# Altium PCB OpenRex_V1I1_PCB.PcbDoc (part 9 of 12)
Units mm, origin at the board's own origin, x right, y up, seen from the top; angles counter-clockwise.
Board outline 70 x 95 mm, 10 copper layers (L1, L2, L3, L4 (PWR), L5 (PWR), L6 (PWR), L7 (PWR), L8, L9, L10), stack 1.632 mm thick; 1080 components, 708 nets, 3831 pads, 2373 vias.
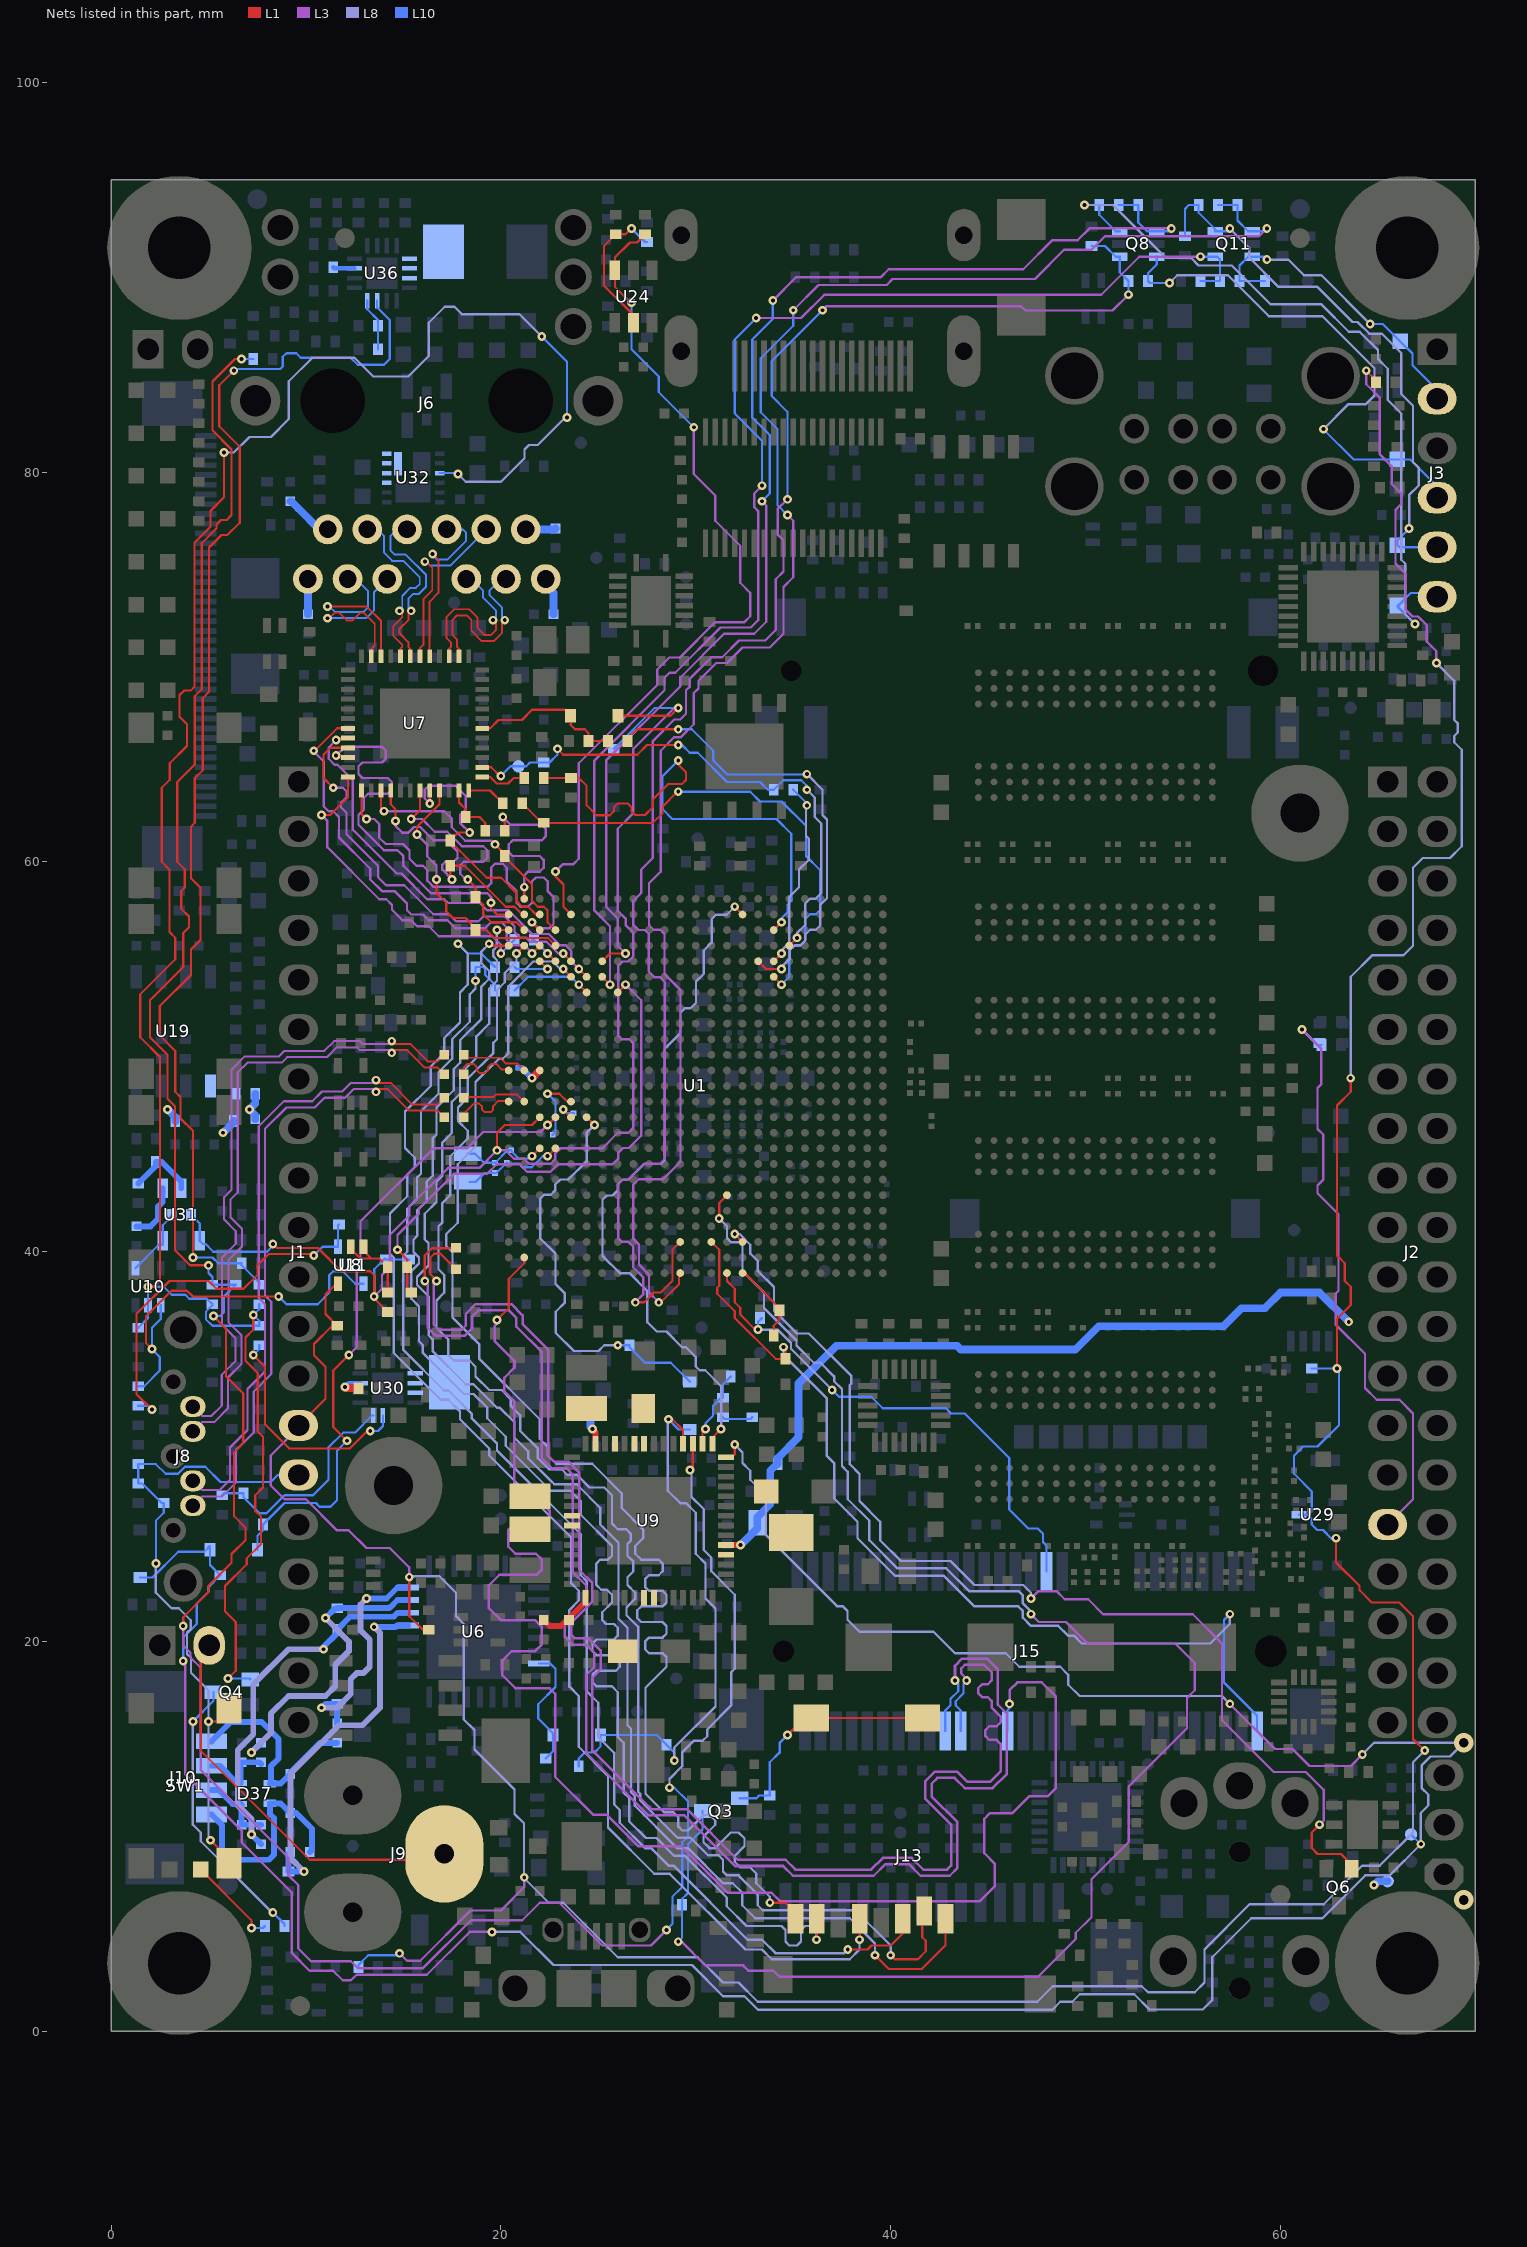
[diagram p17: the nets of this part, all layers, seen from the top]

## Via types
v1: diameter 0.45, hole 0.2, L1 to L10, tented both sides, 2369 vias
v2: diameter 1, hole 0.5, L1 to L10, tented top, 4 vias

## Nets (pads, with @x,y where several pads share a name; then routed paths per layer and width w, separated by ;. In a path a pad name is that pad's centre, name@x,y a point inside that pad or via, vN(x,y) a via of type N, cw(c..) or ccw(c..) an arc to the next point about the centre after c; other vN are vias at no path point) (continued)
PCIE_RX_P: J15.25 U1.B2 | length 83.6
  L1 w0.114: v1(19.8,36.5) 20.4,37.1 20.4,38.605 21.2,39.405 U1.B2@21.2,39.7
  L3 w0.13: v1(19.8,36.5) 19.8,36.3 19.679,36.179 19.679,35.421 20.7,34.4 20.7,34.053 20.18,33.533 20.18,32.82 20.69,32.31 20.69,27.802 21.192,27.3 21.9,27.3 22.5,26.7 22.5,26.4 22.32,26.22 20.867,26.22 20.38,25.733 20.38,24.867 20.747,24.5 21.8,24.5 22.1,24.2 22.1,23.7 21.82,23.42 19.917,23.42 19.38,22.883 19.38,21.717 19.997,21.1 21.747,21.1 22.1,20.747 22.1,19.853 21.757,19.51 20.557,19.51 20.08,19.033 20.08,18.267 20.747,17.6 22.5,17.6 22.79,17.31 22.79,13.057 24.747,11.1 25.447,11.1 27.047,9.5 29.247,9.5 31.647,7.1 33.9,7.1 34.32,6.68 44.58,6.68 45.35,7.45 45.35,8.59 44.8,9.14 44.8,10.9 45.08,11.18 46.233,11.18 47.1,12.047 48.047,12.047 48.476,12.476 48.476,17.177 47.753,17.9 46.5,17.9 46.1,17.5 v1(46.1,16.8)
  L10 w0.114: J15.25@46,15.4 46,16.49 46.1,16.59 v1(46.1,16.8)
PCIE_TX_N: C63.2 J15.31 | length 80.7
  L1 w0.114: v1(16.7,38.5) 16.7,38.525 16.374,38.851 16.374,39.687 16.583,39.896 16.904,39.896 C63.2@17.7,39.1
  L3 w0.13: v1(16.7,38.5) 16.56,38.36 16.56,36.24 16.8,36 18,36 18.2,36.2 18.2,36.8 18.71,37.31 20.543,37.31 21.12,36.733 21.12,36.28 22.42,34.98 22.42,29.528 22.738,29.21 23.49,29.21 24.02,28.68 24.02,23.68 24.7,23 24.7,22.047 23.6,20.947 23.6,20.36 23.8,20.16 24.503,20.16 25.12,19.543 25.12,18.567 24.7,18.147 24.7,14.4 27.7,11.4 29.553,11.4 32.153,8.8 34.613,8.8 35.113,8.3 39,8.3 39.6,8.9 41.072,8.9 41.672,8.3 42.9,8.3 43.1,8.5 43.1,10.6 41.78,11.92 41.78,12.833 42.267,13.32 43.413,13.32 43.933,12.8 45.1,12.8 45.64,13.34 45.64,14.75 45.44,14.95 45.057,14.95 44.857,15.15 44.857,15.45 45.057,15.65 45.44,15.65 45.64,15.85 45.64,16.16 45.18,16.62 45.18,16.95 44.98,17.15 44.69,17.15 44.49,17.35 44.49,17.6 44.69,17.8 44.98,17.8 45.18,18 45.18,18.42 44.8,18.8 43.8,18.8 43.62,18.62 43.62,18.359 43.9,18.079 v1(43.9,18)
  L10 w0.114: J15.31@43.6,15.4 43.6,16.457 43.337,16.72 43.337,16.937 43.737,17.337 43.737,17.837 v1(43.9,18)
PCIE_TX_P: C65.2 J15.33 | length 80.7
  L1 w0.114: v1(16.1,38.5) 16.1,39.8 16.47,40.17 17.67,40.17 C65.2@17.7,40.2
  L3 w0.13: v1(16.1,38.5) 16.24,38.36 16.24,36.107 16.667,35.68 18.133,35.68 18.52,36.067 18.52,36.667 18.843,36.99 20.41,36.99 20.8,36.6 20.8,36.147 22.1,34.847 22.1,29.396 22.606,28.89 23.357,28.89 23.7,28.547 23.7,23.547 24.38,22.867 24.38,22.18 23.28,21.08 23.28,20.227 23.667,19.84 24.37,19.84 24.8,19.41 24.8,18.7 24.38,18.28 24.38,14.267 27.567,11.08 29.42,11.08 32.02,8.48 34.48,8.48 34.98,7.98 39.133,7.98 39.733,8.58 40.939,8.58 41.539,7.98 43.033,7.98 43.42,8.367 43.42,10.733 42.1,12.053 42.1,12.7 42.4,13 43.281,13 43.801,12.48 45.233,12.48 45.96,13.207 45.96,16.293 45.5,16.753 45.5,18.553 44.933,19.12 43.667,19.12 43.3,18.753 v1(43.3,18)
  L10 w0.114: J15.33@42.8,15.4 42.8,16.457 43.063,16.72 43.063,17.05 43.463,17.45 43.463,17.837 v1(43.3,18)
PCIE_WAKE: J15.1 R197.1 U1.P3 | length 49.2
  L1 w0.114: U1.P3@30.8,40.5 31.2,40.1 31.2,38.244 31.1,38.144 31.1,37.844 32,36.944 32,36.6 34.1,34.5 R197.1@34.6,34.5 34.6,35 v1(34.5,35.1)
  L8 w0.12: v1(34.5,35.1) 34.5,34.7 36.715,32.485 36.715,29.541 37.1,29.156 37.1,27.344 38.3,26.144 38.3,25.3 40.234,23.366 42.734,23.366 44.3,21.8 46.544,21.8 46.785,21.559 46.785,21.215 47.2,20.8 48.6,20.8 49.1,20.3 49.4,20.3 49.8,19.9 56.4,19.9 57.4,20.9 v1(57.4,21.4)
  L10 w0.114: v1(57.4,21.4) 57.1,21.1 57.1,17.9 58.8,16.2 J15.1@58.8,15.4
PCIE_WDISN: J15.20 R116.1 U1.R1 | length 27
  L1 w0.114: U1.R1@31.6,38.9 31.6,38.5 32,38.1 32,37.4 32.28,37.12 32.28,36.776 33.056,36 v1(33.2,36)
  L8 w0.12: v1(33.2,36) 34.2,36 34.885,35.315 34.885,35.015 v1(37,32.9)
  L10 w0.114: v1(33.2,36) 33.2,36.4 R116.1@33.4,36.6 ; v1(37,32.9) 37.344,32.556 39,32.556 39.591,31.965 42.835,31.965 43.1,31.7 43.8,31.7 46.085,29.415 46.085,26.77 47.056,25.8 47.544,25.8 47.815,25.529 47.815,25.1 48,24.915 J15.20@48,23.6
PHASE_1V375: L12.1 U30.13 U30.14 U30.15
PHASE_3V3_HDR: L13.1 U36.13 U36.14 U36.15
PMIC_INT: R236.2 R263.1 U1.T24 U9.1 | length 37.8
  L1 w0.114: U9.1@30.85,30.15 30.85,30.45 v1(31.3,30.9) ; v1(32,57.7) U1.T24@32.4,57.3
  L8 w0.12: v1@31.3,31.1 31.3,33.1 30.485,33.915 30.2,33.915 30,34.115 30,34.6 29.5,35.1 29.3,35.1 28.5,35.9 28,35.9 27.515,36.385 27.515,37.985 26.6,38.9 26.1,38.9 25.215,39.785 25.215,42.659 25.441,42.885 25.729,42.885 25.985,43.141 25.985,43.429 26.241,43.685 26.529,43.685 27.344,44.5 28.2,44.5 28.4,44.7 28.4,50.4 29.215,51.215 29.215,52.259 29.441,52.485 29.729,52.485 30.015,52.771 30.015,53.859 30.408,54.252 30.408,55.448 30.815,55.855 30.815,56.7 30.815,57.059 31.041,57.285 31.585,57.285 v1(32,57.7)
  L10 w0.114: v1(31.3,30.9) 31.3,31.4 R236.2@31.4,31.5 31.485,31.415 32.815,31.415 R263.1@32.9,31.5
PMIC_ON_REQ: D29.1 R73.1 U1.D11 | length 33.5
  L1 w0.114: v1(12.1,30.3) 11.4,31 11.4,33.9 v1(12.2,34.7) ; v1(22.4,46.5) U1.D11@22.8,46.9
  L3 w0.12: v1(12.2,34.7) 12.6,35.1 12.6,39 12.8,39.2 12.8,41.556 16.544,45.3 18.256,45.3 19.096,46.14 22.04,46.14 v1(22.4,46.5)
  L10 w0.114: D29.1@7.519,24.7 7.519,25.419 7.8,25.7 R73.1@7.8,26 8.9,27.1 10.515,27.1 10.7,26.915 11.259,26.915 11.6,27.256 11.6,29.8 v1(12.1,30.3)
PMIC_SDWNB: R236.1 R264.1 U9.2 | length 4.1
  L1 w0.114: U9.2@30.35,30.15 30.35,30.75 v1(30.5,30.9)
  L10 w0.114: v1(30.5,30.9) 30.5,31.2 30.885,31.585 30.885,32.085 31.3,32.5 R236.1@31.4,32.5 31.4,33.2 R264.1@31.8,33.6
PMIC_STBY_REQ: D28.2 D36.2 R237.2 R385.1 U9.4 | length 29.5
  L1 w0.114: v1(28.6,31.4) 28.8,31.4 29.35,30.85 U9.4@29.35,30.15
  L8 w0.12: v1(28.6,31.4) 28.565,31.365 28.565,27.735 29.2,27.1 29.5,27.1 30,26.6 30,24.5 30.5,24 30.5,22.2 31.015,21.685 31.015,16.671 28.9,14.556 v1(28.9,13.9)
  L10 w0.114: R237.2@24,13.6 24,14 24.3,14.3 24.8,14.3 25.119,14.619 D36.2@25.119,15.2 28,15.2 R385.1@28.5,14.7 28.9,14.3 v1(28.9,13.9) ; v1(28.6,31.4) 29.119,30.881 D28.2@29.7,30.881
PMIC_STBY_REQ_CPU: D28.1 R266.1 U1.F11 | length 21.8
  L1 w0.114: U1.F11@24.4,46.9 v1(24.8,46.5)
  L8 w0.12: v1(24.8,46.5) 24.415,46.115 24.415,44.655 23.46,43.7 23.056,43.7 22.785,43.429 22.785,43.141 22.559,42.915 22.211,42.915 22.015,42.719 22.015,40.685 22.8,39.9 22.8,38.344 23.285,37.859 23.285,37.385 22.815,36.915 22.815,35.83 23.745,34.9 25.004,34.9 25.304,35.2 v1(26,35.2)
  L10 w0.114: v1(26,35.2) R266.1@26.6,35.2 26.6,35.1 27.4,34.3 28.719,34.3 D28.1@29.7,33.319
PMIC_VDDOTP: C376.1 R261.1 R265.2 TP17.1 U9.47 | length 42.1
  L1 w0.3: U9.47@31.55,24.95 v1(32.3,24.95)
  L1 w0.4: v2@69.35,6.75 v2@69.4,6.7
  L10 w0.4: v1(32.3,24.95) 33.15,25.8 33.15,26.366 33.82,27.036 33.82,28.76 R265.2@34.2,29.14 ; R265.2@34.2,29.1 R265.2@34.2,29.14 ; v1(63.5,36.4) 62,37.9 60,37.9 59.2,37.1 58,37.1 57.075,36.175 50.675,36.175 49.475,34.975 43.6,34.975 43.4,35.175 37.217,35.175 35.275,33.233 35.275,30.475 34.2,29.4 R265.2@34.2,29.14 ; v1(64.8,7.5) 65,7.7 TP17.1@65.5,7.7
  other v2: 69.4,6.74
PMIC_VHALF: C340.2 C342.1 U9.29 | length 3
  L1 w0.3: C342.1@22.2,21.1 22.5,20.8 23.1,20.8 24.35,22.05 U9.29@24.35,22.25
POK_1V375_OPT: R351.1 U30.3 | length 12
  L1 w0.114: v1(7.3,34.7) 7.9,34.1 7.9,31.144 9.144,29.9 12.244,29.9 13.144,30.8 v1(13.3,30.8)
  L10 w0.114: v1(7.3,34.7) 7.6,35 R351.1@7.6,35.2 ; v1(13.3,30.8) 13.7,30.8 13.95,31.05 U30.3@13.95,31.59
POK_3V3_OPT: R333.1 R405.1 U36.3 | length 65.6
  L1 w0.114: v1(4.2,39.7) 4.2,46.2 3.565,46.835 3.565,47.935 3.3,48.2 3.3,50.3 2.5,51.1 2.5,52.6 4.1,54.2 4.1,55.5 4.585,55.985 4.585,58.675 4.1,59.16 4.1,61.8 4.3,62 4.3,64.3 4.7,64.7 4.7,68.396 5.028,68.724 5.028,76.13 5.663,76.765 5.965,76.765 6.6,77.4 6.6,81.3 5.55,82.35 5.55,84.45 v1(6.3,85.2)
  L10 w0.114: v1(4.2,39.7) 5.2,39.7 5.5,39.4 R405.1@6.7,39.4 6.7,39.3 7.6,38.4 R333.1@7.6,38.3 ; v1(6.3,85.2) 6.385,85.285 8.685,85.285 8.815,85.415 8.815,85.915 9,86.1 9.5,86.1 9.733,85.867 12.289,85.867 12.656,85.5 14,85.5 14.3,85.8 14.3,87.8 13.65,88.45 U36.3@13.65,88.8
POK_PMIC: R177.1 R229.1 R404.2 U9.3 | length 145.1
  L1 w0.114: v1(3.7,20.8) 3.7,21.244 5,22.544 5,22.856 6.185,24.041 6.185,24.485 6.9,25.2 6.9,25.84 6.315,26.425 6.315,29.715 6.785,30.185 6.785,32.719 5.9,33.604 5.9,36.05 v1(5.25,36.7) ; v1(5,39.3) 4.056,39.3 3.285,40.071 3.285,47.459 2.9,47.844 2.9,50.1 2,51 2,52.9 3.7,54.6 3.7,56.344 4,56.644 4,57.2 3.6,57.6 3.6,58.494 3.785,58.679 3.785,59.615 3.4,60 3.4,64.1 4.3,65 4.3,68.5 4.657,68.857 4.657,76.351 5.415,77.109 5.415,77.309 5.641,77.535 5.929,77.535 6.185,77.791 6.185,81.159 5.2,82.144 5.2,84.644 6.356,85.8 v1(6.7,85.8) ; v1(29.7,28.8) 29.85,28.95 U9.3@29.85,30.15
  L3 w0.12: v1(3.7,20.8) 3.7,19.8 4.08,19.42 4.08,19.169 4.6,18.649 4.6,13.4 9.1,8.9 9.1,8 9.6,7.5 9.6,4.256 10.262,3.594 12.3,3.594 12.654,3.24 16.008,3.24 18.468,5.7 21.1,5.7 22,6.6 23,6.6 25.2,4.4 27.7,4.4 v1(28.5,5.2)
  L8 w0.12: v1(28.65,12.5) 28.65,12.95 29.3,13.6 29.3,14.3 29.915,14.915 30.359,14.915 30.585,15.141 30.585,15.485 31.815,16.715 31.815,18.415 32,18.6 32,22.4 30.8,23.6 30.8,24.3 30.406,24.694 30.406,26.794 29.785,27.415 29.785,28.715 v1(29.7,28.8)
  L10 w0.114: v1(5,39.3) 5,38.9 5.2,38.7 R177.1@5.2,38.3 R229.1@6.4,38.3 5.8,37.7 5.8,36.9 5.6,36.7 v1(5.25,36.7) ; v1(6.7,85.8) R404.2@7.3,85.8 ; v1(28.5,5.2) 28.8,5.5 28.8,6.9 29.304,7.404 29.304,9.7 29.6,9.996 29.6,11.8 28.9,12.5 v1(28.65,12.5)
POK_SYS: Q4.1 R177.2 R272.1 R333.2 R351.2 U10.2 U32.9 | length 115.5
  L1 w0.114: v1(1.9,38.2) 2.2,38.2 2.51,38.51 2.51,49.99 1.5,51 1.5,53.2 3.3,55 3.3,56.1 3,56.4 3,59.6 2.6,60 2.6,63.8 3.015,64.215 3.015,65.059 3.9,65.944 3.9,67.056 3.515,67.441 3.515,68.559 3.741,68.785 4.085,68.785 4.285,68.985 4.285,76.375 5.1,77.19 5.1,78 5.8,78.7 v1(5.8,81) ; v1(6,18.1) 6.4,18.5 6.4,21 5.85,21.55 5.85,22.85 6.96,23.96 6.96,24.264 7.7,25.004 7.7,26.4 7.4,26.7 7.4,27.5 7.8,27.9 7.8,30.5 7.528,30.772 7.528,33.772 6.9,34.4 6.9,35.6 7.3,36 v1(7.3,36.75)
  L8 w0.12: v1(5.8,81) 6.3,81 7.1,81.8 8.2,81.8 9.122,82.722 9.122,84.657 10.332,85.867 12.489,85.867 13.456,84.9 15.244,84.9 16.3,85.956 16.3,87.66 17.125,88.485 17.615,88.485 18,88.1 20.95,88.1 v1(22.1,86.95) ; v1(17.8,79.9) 18.2,79.5 20.008,79.5 21.215,80.707 21.215,81.159 21.441,81.385 21.893,81.385 23.308,82.8 v1(23.4,82.8)
  L10 w0.114: R272.1@1.4,36.1 1.9,36.6 U10.2@1.9,37.25 v1(1.9,38.2) 2.7,38.2 3.115,37.785 3.815,37.785 4.015,37.585 4.915,37.585 R177.2@5.2,37.3 5.2,37.256 4.865,36.921 4.865,36.535 5.2,36.2 R351.2@7.6,36.2 7.6,36.45 v1(7.3,36.75) 7.6,37.05 R333.2@7.6,37.3 ; v1(6,18.1) 7.1,18.1 Q4.1@7.15,18.05 ; U32.9@16.86,79.95 17.75,79.95 v1(17.8,79.9) ; v1(22.1,86.95) 23.4,85.65 v1(23.4,82.8)
POR_BN: D10.1 R70.1 R158.1 R178.2 R225.1 R350.1 U1.C11 U31.1 | length 71.7
  L1 w0.114: v1(8.3,40.4) 8.515,40.185 10.615,40.185 11.8,39 13.3,39 13.5,38.8 v1(13.5,37.7) 13.5,37.6 R70.1@14.2,36.9 ; v1(19.8,45.2) 19.8,46.1 20.2,46.5 21.6,46.5 U1.C11@22,46.9 ; D10.1@25.919,67.5 D10.1@25.969,67.55 ; D10.1@26.019,67.5 28.7,67.5 v1(29.1,67.9)
  L3 w0.12: v1(13.5,37.7) 13.9,38.1 13.9,38.8 14.3,39.2 14.3,40.856 15.3,41.856 15.3,42.3 17.3,44.3 18.9,44.3 v1(19.8,45.2) 20.244,45.2 20.679,44.765 21.191,44.765 21.441,44.515 22.559,44.515 22.785,44.741 22.785,45.029 23.056,45.3 25.2,45.3 26,46.1 26.544,46.1 26.785,46.341 26.785,50.7 26.585,50.9 26.2,50.9 26.015,51.085 26.015,54.659 26.241,54.885 26.529,54.885 26.8,55.156 26.8,56.36 26.4,56.76 26.4,57.096 26,57.496 26,61.7 26.8,62.5 26.8,65.8 28.9,67.9 v1(29.1,67.9)
  L10 w0.114: R350.1@4.1,41.9 4.55,41.45 U31.1@4.55,40.55 4.7,40.4 4.844,40.4 5.244,40 8,40 8.3,40.3 v1(8.3,40.4) ; v1(13.5,37.7) 13.5,39.1 R158.1@14.05,39.65 ; R158.1@14.1,39.6 R225.1@15.3,39.6 ; R178.2@25.8,65.8 27.9,67.9 v1(29.1,67.9)
POR_CT: C413.1 U31.4 | length 2.9
  L10 w0.3: C413.1@1.3,41.3 2.021,41.3 2.41,41.689 2.41,42.31 2.65,42.55 U31.4@2.65,43.25
POR_R_BN: R350.2 U10.4 U31.3 | length 3.6
  L10 w0.114: U10.4@1.25,39.15 2.45,40.35 2.65,40.35 U31.3@2.65,40.55 2.65,41.35 3.1,41.8 R350.2@3.1,41.9
PWM2_OUT_R: J2.31 R367.2 R369.2 | length 30.8
  L3 w0.12: v1(61.1,51.4) 62.1,50.4 62.1,48.6 61.9,48.4 61.9,46.3 62.2,46 62.2,43.7 61.9,43.4 61.9,43 62.98,41.92 62.98,37.995 62.83,37.845 62.83,36.27 64.34,34.76 64.34,33 64.94,32.4 66.1,32.4 66.8,31.7 66.8,27.3 J2.31@65.5,26
  L10 w0.114: v1(61.1,51.4) 61.9,50.6 R367.2@62.1,50.6
PWR_LED_GRN_D: D22.1 R379.1 | length 4.8
  L1 w0.114: D22.1@4.6,8.3 7.2,5.7 v1(7.2,5.3)
  L10 w0.114: v1(7.2,5.3) 7.8,5.3 R379.1@7.9,5.4
PWR_LED_GRN_Q: Q4.3 R379.2 | length 14.4
  L8 w0.12: v1(4.2,15.9) 4.2,10.6 4.6,10.2 4.6,9.756 8.256,6.1 v1(8.3,6.1)
  L10 w0.114: v1(4.2,15.9) 5.25,16.95 Q4.3@5.25,17.4 ; v1(8.3,6.1) 8.9,5.5 R379.2@8.9,5.4
PWR_SEL: J9.3 JP1.2 | length 20.5
  L1 w0.114: JP1.2@5.04,19.78 5.04,19.6 4.6,19.16 4.6,14.4 10.2,8.8 16.1,8.8 16.4,9.1 J9.3@17.1,9.1
PWRON: D29.2 D39.2 R262.1 TP6.1 U9.56 | length 150.9
  L1 w0.114: U9.56@31.55,29.45 31.85,29.45 32,29.6 v1(32,30.1)
  L3 w0.12: v1(3.7,19) 3.8,18.9 3.8,13.2 6.7,10.3 6.7,9.7 9.265,7.135 9.265,4.035 10.2,3.1 11.4,3.1 11.885,2.615 12.315,2.615 12.6,2.9 16.2,2.9 18.4,5.1 v1(19.55,5.1) ; v1(57.4,16.8) 59.715,14.485 60.615,14.485 61.485,13.615 63.615,13.615 v1(64.2,14.2)
  L8 w0.12: v1(19.55,5.1) 21,5.1 22.7,3.4 29.8,3.4 31.398,1.802 32.502,1.802 33.204,1.1 48.285,1.1 48.7,1.515 49.315,1.515 49.7,1.9 52.5,1.9 53.285,1.115 56.015,1.115 56.5,1.6 56.5,3.8 58.5,5.8 62.15,5.8 64.35,8 65.6,8 v1(67.2,9.6) 67.2,11.2 67.585,11.585 67.585,12.144 67.24,12.489 67.24,13.64 67.7,14.1 68.7,14.1 v2(69.4,14.8) 64.8,14.8 v1(64.2,14.2) ; v1(32,30.1) 32.4,29.7 32.4,29.156 32.8,28.756 32.8,28.3 33.6,27.5 33.6,25.456 37.241,21.815 37.529,21.815 37.785,21.559 37.785,21.115 38.4,20.5 42.2,20.5 43.3,19.4 45.9,19.4 46.6,18.7 48.7,18.7 49.115,18.285 49.115,17.785 49.7,17.2 57,17.2 v1(57.4,16.8)
  L10 w0.114: D39.2@1.5,23.281 2.125,23.281 3.444,24.6 4.781,24.6 5.081,24.9 D29.2@5.081,24.7 5.081,23.919 R262.1@5.6,23.4 5,22.8 5,22.544 4.4,21.944 4.4,20.9 3.7,20.2 v1(3.7,19) ; TP6.1@66.7,10.1 v1(67.2,9.6)
RGMII_INT: R88.2 R89.1 TP27.1 U1.W22 U7.38 | length 28.6
  L1 w0.114: U7.38@19.04,64.85 19.506,64.85 19.956,64.4 v1(20,64.4) ; v1(22.9,65.8) 23.2,65.5 27,65.5 27.5,66 v1(29.1,66) ; U1.W22@34.8,55.7 v1(35.2,56.1)
  L8 w0.12: v1(35.2,56.1) 35.2,56.356 35.615,56.771 35.615,57.2 35.615,57.859 35.871,58.115 36.159,58.115 36.44,58.396 36.44,61.96 36.1,62.3 36.1,63.3 v1(35.7,63.7)
  L10 w0.114: v1(20,64.4) 20.5,64.9 TP27.1@20.9,64.9 21.3,64.9 21.5,65.1 R89.1@22.2,65.1 22.5,65.1 22.9,65.5 v1(22.9,65.8) ; v1(29.1,66) 29.296,66 29.696,65.6 30.1,65.6 31.6,64.1 33.3,64.1 33.7,63.7 R88.2@34,63.7 34.49,64.19 35.41,64.19 35.7,63.9 v1(35.7,63.7)
RGMII_INT_R: R88.1 U1.V21 | length 9.9
  L1 w0.114: U1.V21@34,54.9 v1(34.4,55.3)
  L8 w0.12: v1(34.4,55.3) 34.4,55.455 34.8,55.855 34.8,58.2 35.3,58.7 35.3,59.6 35.8,60.1 35.8,61.194 35.653,61.341 35.653,62.853 v1(35.7,62.9)
  L10 w0.114: R88.1@35,63.7 35.7,63 v1(35.7,62.9)
RGMII_MDC: R85.1 R87.1 U1.V20 | length 26.7
  L1 w0.114: R85.1@21.1,63 22.1,62 R87.1@22.2,62 27.8,62 28.3,62.5 28.3,62.844 29.056,63.6 v1(29.1,63.6) ; U1.V20@34,54.1 v1(34.4,53.7)
  L10 w0.114: v1(29.1,63.6) 32.8,63.6 33.3,63.1 34.4,63.1 35.653,61.847 35.653,60.302 36.385,59.571 36.385,57.541 36.159,57.315 35.871,57.315 35.615,57.059 35.615,55.971 35.329,55.685 35.041,55.685 34.8,55.444 34.8,54.1 v1(34.4,53.7)
RGMII_MDIO: R86.1 R162.1 U1.V23 | length 26.8
  L1 w0.114: R86.1@22.2,64.3 R162.1@23.6,64.3 24,64.3 24.4,63.9 24.4,62.9 24.91,62.39 25.59,62.39 25.8,62.6 25.8,62.8 26,63 26.5,63 26.7,62.8 26.7,62.6 26.9,62.4 27.4,62.4 27.8,62.8 27.8,63.2 28.6,64 29.3,64 29.5,64.2 29.5,64.6 29.1,65 v1(29.1,65.2) ; U1.V23@34,56.5 v1(34.4,56.9)
  L10 w0.114: v1(29.1,65.2) 28.3,64.4 28.3,62.7 28.8,62.2 34.144,62.2 34.9,61.444 34.9,58 34.7,57.8 34.7,57.4 34.4,57.1 v1(34.4,56.9)
RGMII_R_MDC: R85.2 U7.36 | length 2
  L1 w0.114: U7.36@18.35,63.66 19.44,63.66 R85.2@20.1,63
RGMII_R_MDIO: R86.2 U7.37 | length 2.4
  L1 w0.114: U7.37@19.04,64.35 19.45,64.35 19.785,64.015 20.371,64.015 20.656,64.3 R86.2@21.2,64.3
RGMII_R_RXCLK: R83.2 R101.2 U7.35 | length 3
  L1 w0.114: U7.35@17.85,63.66 17.85,63.05 18.2,62.7 R101.2@18.2,62.3 18.9,62.3 19.2,62 R83.2@19.2,61.6
RGMII_R_TXCLK: R35.1 U1.D21 | length 1.7
  L1 w0.114: v1(22.4,55.3) U1.D21@22.8,54.9
  L10 w0.114: R35.1@21.6,56 R35.1@21.7,56 v1(22.4,55.3)
RGMII_RSTN: D10.2 R75.1 R180.1 U7.42 | length 8.1
  L1 w0.114: U7.42@19.04,66.85 19.45,66.85 19.88,67.28 21.08,67.28 21.6,67.8 23.281,67.8 D10.2@23.581,67.5 23.581,67.019 23.8,66.8 24.3,66.8 24.5,66.6 R75.1@24.5,66.2 25.4,66.2 R180.1@25.5,66.1
RGMII_RSTN_R: R180.2 U1.U21 | length 23.9
  L1 w0.114: R180.2@26.4,66.2 27,66.8 v1(29.1,66.8) ; U1.U21@33.2,54.9 33.6,54.5 v1(34.4,54.5)
  L8 w0.12: v1(34.4,54.5) 34.4,54.6 34.815,55.015 34.815,55.459 35.071,55.715 35.359,55.715 35.615,55.971 35.615,56.259 35.871,56.515 36.159,56.515 36.385,56.741 36.385,57.785 36.73,58.13 36.73,62.17 36.5,62.4 36.5,63.7 v1(35.7,64.5)
  L10 w0.114: v1(29.1,66.8) 29.8,66.8 30.9,65.7 30.9,65.2 31.62,64.48 35.68,64.48 v1(35.7,64.5)
RGMII_RXCLK: R83.1 U1.B25 | length 10.8
  L1 w0.114: v1(20.1,62.3) 20.2,62.2 R83.1@20.2,61.6 ; U1.B25@21.2,58.1 v1(21.2,58.7)
  L3 w0.12: v1(20.1,62.3) 20.5,61.9 22.095,61.9 22.295,61.7 22.295,61.3 22.095,61.1 20.605,61.1 20.405,60.9 20.405,60.5 20.605,60.3 22,60.3 ; v1(21.2,58.7) 21.2,59.3 21.4,59.5 21.995,59.5 22.195,59.7 22.195,60.1 21.995,60.3
RGMII_RXD0: R98.1 U1.C24 U7.32 | length 13.7
  L1 w0.114: v1(16.35,63) U7.32@16.35,63.66 ; v1(18.4,61.5) 17.8,61.5 R98.1@17.4,61.1 17.4,61.056 19.27,59.186 20.014,59.186 20.8,58.4 20.8,57.991 21.091,57.7 21.4,57.7 21.8,57.3 U1.C24@22,57.3
  L3 w0.12: v1(16.35,63) 16.1,63.25 16.1,63.7 16.3,63.9 17.675,63.9 18.2,63.375 18.2,62.7 17.9,62.4 17.9,62 v1(18.4,61.5)
RGMII_RXD1: R97.1 U1.B23 U7.31 | length 13.6
  L1 w0.114: v1(15.4,62.2) 15.85,62.65 U7.31@15.85,63.66 ; v1(18.3,59.1) 18.7,58.7 R97.1@18.7,58.2 19.1,57.8 19.1,57.3 19.5,56.9 20.8,56.9 U1.B23@21.2,56.5
  L3 w0.12: v1(15.4,62.2) 15.956,62.2 16.61,61.545 17.255,61.545 18,60.8 19.1,60.8 19.3,60.6 19.3,60.2 19.1,60 18.1,60 17.915,59.815 17.915,59.385 18.2,59.1 v1(18.3,59.1)
RGMII_RXD2: R96.1 U1.B24 U7.28 | length 13.7
  L1 w0.114: U7.28@14.35,63.66 14.35,62.95 14.6,62.7 v1(14.6,62.1) ; v1(17.5,59.1) 17.4,59.2 R96.1@17.4,59.8 18.144,59.8 20.244,57.7 20.695,57.7 21.095,57.3 U1.B24@21.2,57.3
  L3 w0.12: v1(14.6,62.1) 14.6,61.844 14.944,61.5 15.256,61.5 15.541,61.785 15.859,61.785 16.529,61.115 17.185,61.115 17.775,60.525 17.775,60.2 17.575,60 17.15,60 17,59.85 17,59.6 v1(17.5,59.1)
RGMII_RXD3: R95.1 U1.D23 U7.27 | length 13.7
  L1 w0.114: U7.27@13.85,63.66 13.85,62.75 v1(14,62.6) ; v1(19.7,60.9) 20.2,60.4 R95.1@20.2,60.3 20.2,60.244 21.6,58.844 21.6,57.991 21.891,57.7 22.2,57.7 22.4,57.5 22.4,56.9 U1.D23@22.8,56.5
  L3 w0.12: v1(14,62.6) 17.1,62.6 17.478,62.222 17.478,61.778 18.176,61.08 19.52,61.08 v1(19.7,60.9)
RGMII_RXDV: R91.1 U1.D22 U7.33 | length 13.7
  L1 w0.114: v1(15.7,61.4) 15.7,61.8 16.85,62.95 U7.33@16.85,63.66 ; v1(16.7,59.1) 16.7,58.4 17.2,57.9 17.2,57.456 17.541,57.115 18.185,57.115 18.7,56.6 R91.1@18.7,56.5 19.244,56.5 19.644,56.1 22.4,56.1 U1.D22@22.8,55.7
  L3 w0.12: v1(15.7,61.4) 16.215,60.885 16.215,60.291 16.7,59.806 v1(16.7,59.1)
RGMII_TXCLK: R35.2 U7.24 | length 17.1
  L1 w0.114: v1(10.8,62.4) 11.244,62.4 12.16,63.316 U7.24@12.16,64.35
  L3 w0.12: v1(10.8,62.4) 11.1,62.1 11.1,60.744 13.759,58.085 14.115,58.085 14.415,57.785 14.415,57.541 14.948,57.007 15.393,57.007 15.7,56.7 16.3,56.7 16.815,56.185 19.559,56.185 20,55.744 v1(20,55.3)
  L10 w0.114: v1(20,55.3) R35.2@20.7,56
RGMII_TXD0: U1.C22 U7.19 | length 21.5
  L1 w0.114: v1(10.4,65.7) 10.456,65.7 11.606,66.85 U7.19@12.16,66.85 ; v1(21.6,55.3) U1.C22@22,55.7
  L3 w0.12: v1(10.4,65.7) 10.4,65.66 10.915,65.145 10.915,62.841 11.156,62.6 11.4,62.6 11.696,62.304 11.696,61.248 13.3,59.644 13.3,59.1 13.9,58.5 14.544,58.5 15.185,57.859 15.185,57.515 15.4,57.3 16,57.3 16.3,57 17.26,57 17.66,56.6 19.2,56.6 19.5,56.9 20.027,56.9 20.3,56.627 20.3,56 20.573,55.727 21.2,55.727 21.6,55.327 v1(21.6,55.3)
RGMII_TXD1: U1.F20 U7.20 | length 21.5
  L1 w0.114: v1(11.55,66.25) 11.65,66.35 U7.20@12.16,66.35 ; v1(24,54.5) U1.F20@24.4,54.1
  L3 w0.12: v1(11.55,66.25) 11.165,65.865 11.165,65.291 11.471,64.985 11.615,64.985 12.4,64.2 12.4,61.656 14.656,59.4 14.9,59.4 16.215,58.085 17.1,58.085 17.3,57.885 18.915,57.885 19.285,57.515 20.385,57.515 21.6,56.3 22.456,56.3 23.041,55.715 23.329,55.715 23.615,55.429 23.615,54.885 v1(24,54.5)
RGMII_TXD2: U1.E21 U7.21 | length 21.5
  L1 w0.114: v1(11.4,63.8) 10.9,64.3 10.9,65.5 11.25,65.85 U7.21@12.16,65.85 ; v1(23.2,55.3) U1.E21@23.6,54.9
  L3 w0.12: v1(11.4,63.8) 11.9,63.8 12.08,63.62 12.08,63.3 11.8,63.02 11.8,62.8 12.08,62.52 12.08,61.42 13.7,59.8 13.7,59.206 14.106,58.8 15.044,58.8 16.529,57.315 17.341,57.315 17.706,56.95 18.85,56.95 19.1,57.2 20.2,57.2 20.7,56.7 20.7,56.4 21,56.1 21.3,56.1 21.5,55.9 22.344,55.9 22.944,55.3 v1(23.2,55.3)
RGMII_TXD3: U1.A24 U7.22 | length 21.4
  L1 w0.114: v1(11.55,65.45) 11.65,65.35 U7.22@12.16,65.35 ; v1(19.5,57.9) 19.5,57.6 19.8,57.3 U1.A24@20.4,57.3
  L3 w0.12: v1(11.55,65.45) 12,65.9 13.9,65.9 14.1,65.7 14.1,65.3 13.9,65.1 12.9,65.1 12.7,64.9 12.7,64.5 12.9,64.3 14.2,64.3 14.4,64.1 14.4,63.7 14.2,63.5 13.2,63.5 12.965,63.265 12.965,62.665 12.7,62.4 12.7,61.9 14,60.6 14.7,60.6 15,60.3 15,59.8 16.415,58.385 19.315,58.385 19.5,58.2 v1(19.5,57.9)
RGMII_TXEN: U1.C23 U7.25 | length 21.5
  L1 w0.114: U7.25@12.85,63.66 12.85,62.45 v1(13.1,62.2) ; v1(21.6,56.9) U1.C23@22,56.5
  L3 w0.12: v1(13.1,62.2) 13.5,62.2 13.765,61.935 13.765,61.241 14.091,60.915 14.985,60.915 15.315,60.585 15.315,60.16 15.675,59.8 16,59.8 16.22,59.58 16.22,59.036 16.541,58.715 19.315,58.715 19.5,58.9 19.5,59.7 19.7,59.9 20.1,59.9 20.3,59.7 20.3,59 20.8,58.5 20.8,57.9 21,57.7 21.4,57.7 21.6,57.9 21.6,59 21.8,59.2 22.2,59.2 22.4,59 22.4,58.5 22.7,58.2 22.7,56.8 22.5,56.6 21.9,56.6 v1(21.6,56.9)
RST_BTN_HDR: J1.15 R140.1 R141.2 R347.1 SW1.1 SW1.2 | length 33.7
  L1 w0.114: v1(5,15.9) 5.375,15.9 SW1.1@6.05,16.575 ; v1(5.1,9.8) 6.05,8.85 SW1.2@6.05,8.625
  L8 w0.12: v1(2.3,24) 2.3,22.5 3.1,21.7 3.47,21.7 4.085,21.085 4.085,20.641 3.9,20.456 3.9,19.362 4.1,19.162 4.1,18.4 5,17.5 v1(5,15.9) 5,9.9 v1(5.1,9.8)
  L10 w0.114: v1(2.3,24) 2.3,26.2 2.7,26.6 R140.1@2.7,27.1 2.6,27.1 1.6,28.1 R347.1@1.4,28.1 R141.2@1.4,29.1 2.3,29.1 2.8,28.6 3.436,28.6 3.8,28.964 4.836,28.964 5.62,28.18 8.2,28.18 8.56,28.54 J1.15@9.62,28.54
RSTINN: R68.1 R348.2 U8.1 | length 19.7
  L1 w0.114: v1(2.1,31.9) 1.3,32.7 1.3,36.8 3,38.5 5,38.5 5.4,38.1 6.8,38.1 7.52,38.82 7.52,39.32 8.085,39.885 10.315,39.885 v1(10.4,39.8)
  L10 w0.114: R348.2@1.4,32.1 1.9,32.1 v1(2.1,31.9) ; v1(10.4,39.8) 10.85,40.25 U8.1@11.65,40.25 11.65,41.35 R68.1@11.7,41.4
RSTINN_BUFF: R59.1 U8.4 U10.1 | length 20.5
  L1 w0.114: v1(2.1,35) 1.8,35.3 1.8,36.7 3.1,38 3.9,38 4.2,37.7 v1(8.6,37.7)
  L10 w0.114: R59.1@1.4,33.1 1.7,33.1 2.5,33.9 2.5,34.6 v1(2.1,35) 2.1,36.1 2.55,36.55 U10.1@2.55,37.25 ; v1(8.6,37.7) 9,37.3 10.6,37.3 11.2,37.9 11.2,38.8 11.4,39 11.882,39 12.532,38.35 U8.4@12.95,38.35 ; v1@8.6,37.8 v1@8.65,37.75
RSTOUTN: J1.14 R144.2 R155.2 R218.2 R281.2 R318.1 U11.4 U29.2 | length 199.5
  L1 w0.114: J1.14@9.62,31.08 11,32.46 11,34.1 10.415,34.685 10.415,35.259 11.356,36.2 R144.2@11.6,36.2 11,36.8 11,37.8 11.55,38.35 U11.4@11.65,38.35 ; v1(15.3,23.3) 15.3,21.3 16,20.6 R281.2@16.3,20.6 ; v1(62.85,25.3) 62.85,24.054 64.06,22.844 64.06,22.625 64.685,22 66.1,22 66.8,21.3 66.8,15 v1(67.4,14.4) ; v1(62.9,34) 62.9,36.565 63.6,37.265 63.6,38.2 63.3,38.5 63.3,39.4 62.9,39.8 62.9,47.5 63.6,48.2 v1(63.6,48.9) ; v1(64.4,85.2) 64.9,84.7 R218.2@64.9,84.6
  L3 w0.12: J1.14@9.62,31.08 9.62,30.976 8.19,29.546 8.19,28.01 8.9,27.3 10,27.3 11.6,25.7 12.2,25.7 13.1,24.8 14.3,24.8 15.3,23.8 v1(15.3,23.3) ; v1(14.8,4) 15.185,3.615 15.859,3.615 18.444,6.2 20,6.2 21.2,7.4 v1(21.2,7.9) ; v1(64.4,85.2) 64.4,84.5 65.1,83.8 65.1,80.9 65.7,80.3 65.7,79.4 66.2,78.9 66.2,78.356 65.9,78.056 65.9,75.3 66.415,74.785 66.415,72.941 66.771,72.585 67.059,72.585 67.5,72.144 67.5,71.3 68,70.8 v1(68,70.2)
  L8 w0.12: v1(15.3,23.3) 15.345,23.345 16.855,23.345 17.7,22.5 17.7,21.3 18.1,20.9 18.1,16 18.647,15.453 18.647,14.453 20.7,12.4 20.7,11.156 21.185,10.671 21.185,7.915 v1(21.2,7.9) 21.2,7.856 22.456,6.6 23.2,6.6 26,3.8 30.1,3.8 31.4,2.5 32.2,2.5 33.18,1.52 47.52,1.52 48.315,2.315 52.885,2.315 53.2,2 55.6,2 56.1,2.5 56.1,4.2 58.415,6.515 62.215,6.515 64.2,8.5 65.096,8.5 66.8,10.204 66.8,13.8 v1(67.4,14.4) ; v1(63.6,48.9) 63.6,54.1 64.7,55.2 66.3,55.2 66.8,55.7 66.8,59.7 67.3,60.2 68.7,60.2 69.3,60.8 69.3,65.756 68.915,66.141 68.915,66.459 69.1,66.644 69.1,67.1 68.915,67.285 68.915,69.285 v1(68,70.2)
  L10 w0.114: R155.2@12.7,3.3 12.7,3.4 13.2,3.9 14.7,3.9 v1(14.8,4) ; U29.2@60.95,26.5 61.4,26.5 ; R318.1@61.6,34 v1(62.9,34) 63,33.9 63,31.1 61.9,30 61.156,30 60.7,29.544 60.7,28.6 61.6,27.7 61.6,26.7 61.4,26.5 ; v1(62.85,25.3) 62.594,25.3 62.179,25.715 61.891,25.715 61.6,26.006 61.6,26.3 61.4,26.5
RSTOUTN_BUFF: R51.2 R70.2 U11.1 U11.2 | length 4.5
  L1 w0.114: U11.2@12.3,40.25 12.3,40.144 12.8,39.644 13.356,39.644 ; U11.1@12.95,40.25 12.95,40.05 13.356,39.644 ; R70.2@14.2,37.9 R51.2@14.2,39.2 13.756,39.644 13.356,39.644
RSTOUTN_R: R49.1 R51.1 U1.H19 | length 27.1
  L1 w0.114: v1(14.7,40.1) 15.2,39.6 R51.1@15.2,39.2 15.2,38.1 R49.1@15.4,37.9 ; U1.H19@26,53.3 v1(26.4,53.7)
  L3 w0.12: v1(14.7,40.1) 14.7,40.86 15.8,41.96 15.8,42.2 17.59,43.99 19.29,43.99 19.785,44.485 20.962,44.485 21.347,44.1 22.54,44.1 22.925,44.485 25.729,44.485 26.015,44.771 26.015,45.059 26.271,45.315 26.559,45.315 27.2,45.956 27.2,52.9 v1(26.4,53.7)
RTC_XTALI: C211.1 R168.1 U1.D9 Y2.1 | length 5.3
  L1 w0.114: v1(22.4,44.9) U1.D9@22.8,45.3
  L10 w0.114: Y2.1@18.4,43.575 18.7,43.575 19.16,44.035 R168.1@19.7,44.035 19.77,44.035 C211.1@20.3,44.565 20.36,44.505 20.939,44.505 21.109,44.335 21.579,44.335 22.144,44.9 v1(22.4,44.9)
RTC_XTALO: C212.1 R168.2 U1.C9 Y2.2 | length 4.6
  L1 w0.114: v1(21.6,44.9) U1.C9@22,45.3
  L10 w0.114: Y2.2@18.3,45.025 18.675,45.025 19.135,44.565 R168.2@19.7,44.565 19.709,44.565 20.344,45.2 C212.1@20.535,45.2 20.535,45.165 20.915,44.785 21.485,44.785 v1(21.6,44.9)
SATA_C_RX_N: C69.1 U1.A14 | length 3.4
  L1 w0.1: C69.1@18.1,49.1 18.1,49.45 18.28,49.63 18.6,49.63 18.75,49.48 18.75,49.317 18.9,49.168 19.2,49.168 19.35,49.317 19.35,49.48 19.5,49.63 19.761,49.63 20.051,49.34 20.36,49.34 U1.A14@20.4,49.3
SATA_C_RX_P: C70.1 U1.B14 | length 3.4
  L1 w0.1: C70.1@18.1,50.1 18.25,49.95 19.95,49.95 20.24,49.66 20.84,49.66 U1.B14@21.2,49.3
SATA_C_TX_N: C71.1 U1.B12 | length 3.3
  L1 w0.1: C71.1@18.1,47.9 18.1,47.932 19.615,47.932 19.742,48.06 20.84,48.06 U1.B12@21.2,47.7
SATA_C_TX_P: C72.1 U1.A12 | length 3.3
  L1 w0.1: C72.1@18.1,46.9 18.1,47.075 18.637,47.612 18.875,47.612 19.025,47.462 19.025,47.313 19.175,47.163 19.475,47.163 19.605,47.293 19.605,47.47 19.875,47.74 20.36,47.74 U1.A12@20.4,47.7
SATA_REXT: R99.2 U1.C14 | length 1.5
  L1 w0.4: v1(21.6,48.9) U1.C14@22,49.3
  L10 w0.3: R99.2@20.9,49.435 21.065,49.435 v1(21.6,48.9)
SATA_RX_N: C69.2 J8.5 | length 32.6
  L1 w0.1: v1(14.4,50.2) 14.54,50.34 15.207,50.34 16.107,49.44 16.76,49.44 C69.2@17.1,49.1
  L3 w0.11: J8.5@4.2,30.78 4.675,31.255 5.288,31.255 6,31.967 6,33.547 6.7,34.247 6.7,35.7 6.02,36.38 6.02,39.567 6.72,40.267 6.72,41.18 6.12,41.78 6.12,42.667 6.5,43.047 6.5,49.2 7,49.7 8.753,49.7 9.033,49.98 11.08,49.98 11.58,50.48 12.627,50.48 12.767,50.34 14.26,50.34 v1(14.4,50.2)
SATA_RX_P: C70.2 J8.6 | length 32.6
  L1 w0.1: v1(14.4,50.8) 14.54,50.66 15.34,50.66 16.24,49.76 16.76,49.76 C70.2@17.1,50.1
  L3 w0.11: J8.6@4.2,32.05 4.675,31.575 5.155,31.575 5.68,32.1 5.68,33.68 6.38,34.38 6.38,35.567 5.7,36.247 5.7,39.7 6.4,40.4 6.4,41.047 5.8,41.647 5.8,42.8 6.18,43.18 6.18,49.333 6.867,50.02 8.62,50.02 8.9,50.3 10.947,50.3 11.447,50.8 12.76,50.8 12.9,50.66 14.26,50.66 v1(14.4,50.8)
SATA_TX_N: C71.2 J8.3 | length 32.5
  L1 w0.1: v1(13.6,48.8) 13.74,48.66 14.34,48.66 15.44,47.56 16.76,47.56 C71.2@17.1,47.9
  L3 w0.11: J8.3@4.2,28.24 4.675,27.765 5.565,27.765 6.1,28.3 6.1,29.953 7,30.853 7,32.953 7.9,33.853 7.9,37.3 7.58,37.62 7.58,46.433 8.867,47.72 10.32,47.72 10.82,48.22 11.867,48.22 12.307,48.66 13.46,48.66 v1(13.6,48.8)
SATA_TX_P: C72.2 J8.2 | length 32.5
  L1 w0.1: v1(13.6,48.2) 13.74,48.34 14.207,48.34 15.307,47.24 16.76,47.24 C72.2@17.1,46.9
  L3 w0.11: J8.2@4.2,26.97 4.675,27.445 5.698,27.445 6.42,28.167 6.42,29.82 7.32,30.72 7.32,32.82 8.22,33.72 8.22,37.433 7.9,37.753 7.9,46.3 9,47.4 10.453,47.4 10.953,47.9 12,47.9 12.44,48.34 13.46,48.34 v1(13.6,48.2)
SD2_ACT: Q6.1 U1.T3 | length 56.6
  L1 w0.114: v1(32,40.9) U1.T3@32.4,40.5 ; v1(62,10.6) 61.6,10.2 61.6,9.4 61.9,9.1 63.1,9.1 63.65,8.55 Q6.1@63.65,8.35
  L3 w0.12: v1(47.2,22.2) 47.585,22.585 48.515,22.585 48.935,22.165 50.135,22.165 50.9,21.4 55.5,21.4 57,19.9 57,15.956 59.656,13.3 61.3,13.3 62.215,12.385 62.215,10.815 v1(62,10.6)
  L8 w0.12: v1(32,40.9) 32.256,40.9 32.8,40.356 32.8,39.9 33.185,39.515 33.185,39.015 34.015,38.185 34.015,36.985 35.2,35.8 35.8,35.8 37.985,33.615 37.985,33.241 37.9,33.156 37.9,29.1 38.4,28.6 38.4,27.2 39.46,26.14 39.46,25.196 40.524,24.132 43.068,24.132 44.3,22.9 46.8,22.9 47.2,22.5 v1(47.2,22.2)
SD2_CD: Q3.3 R150.1 U1.R6 | length 87
  L1 w0.114: v1(31.2,41.7) 31.2,42.5 U1.R6@31.6,42.9
  L3 w0.12: v1(29.1,4.6) 29.264,4.6 30.482,3.382 32.428,3.382 32.7,3.11 33.99,3.11 34.3,2.8 47.566,2.8 49.5,4.734 49.5,5.056 50.3,5.856 50.3,7.8 52.223,9.723 52.223,12.567 55.2,15.544 55.2,17.1 55.6,17.5 55.6,18.9 54.6,19.9 50.1,19.9 49,21 47.6,21 v1(47.2,21.4)
  L8 w0.12: v1(31.2,41.7) 31.6,41.3 31.6,40.7 31.815,40.485 32.215,40.485 32.4,40.3 32.4,39 33.5,37.9 33.5,37.104 35.165,35.439 35.165,35.191 36.056,34.3 36.4,34.3 37.1,33.6 37.1,33.356 37.5,32.956 37.5,29 37.8,28.7 37.8,27.3 38.9,26.2 38.9,25.2 40.351,23.749 42.851,23.749 44.015,22.585 46.559,22.585 46.785,22.359 46.785,21.955 47.2,21.54 v1(47.2,21.4)
  L10 w0.114: v1(29.1,4.6) 29.3,4.8 R150.1@29.3,6.5 29.3,6.8 29.6,7.1 29.6,9.6 30.35,10.35 Q3.3@30.35,11.3
SD2_CDN: J13.9 J13.10 Q3.1 R201.1 | length 12.4
  L1 w0.123: v1(34.7,15.2) 35.575,16.075 J13.10@35.925,16.075 J13.9@41.625,16.075
  L10 w0.123: Q3.1@32.25,11.95 33.1,11.95 33.25,12.1 R201.1@33.8,12.1 33.8,13.8 34.3,14.3 34.3,14.8 v1(34.7,15.2)
SD2_CLK: J13.5 R153.2 | length 72.8
  L1 w0.114: v1(38.4,4.7) 38.415,4.715 J13.5@38.415,5.775
  L8 w0.12: v1(17.8,55.8) 18.3,55.3 18.3,53.7 17.9,53.3 17.9,51.756 17.1,50.956 17.1,50.2 16.4,49.5 16.4,48.5 15.085,47.185 15.085,45.315 15.585,44.815 15.585,44.341 15.2,43.956 15.2,42.844 14.315,41.959 14.315,39.885 14.5,39.7 14.5,34.8 16.9,32.4 17.3,32.4 17.9,31.8 17.9,31.4 19.4,29.9 19.4,29.544 23.6,25.344 23.6,23 24,22.6 24,22.1 23.515,21.615 23.515,17.685 24,17.2 24,14.6 25.5,13.1 25.5,10.456 27.871,8.085 28.659,8.085 32.544,4.2 33.4,4.2 33.9,3.7 37.9,3.7 38.4,4.2 v1(38.4,4.7)
  L10 w0.114: v1(17.8,55.8) 18.3,55.3 19,55.3 R153.2@19.7,54.6
SD2_CLK_R: R153.1 U1.C21 | length 2.3
  L1 w0.114: U1.C21@22,54.9 v1(22.4,54.5)
  L10 w0.114: R153.1@20.7,54.6 20.8,54.5 v1(22.4,54.5)
SD2_CMD: J13.3 R143.1 R152.2 | length 70.5
  L1 w0.114: v1(37.8,4.2) 38.815,4.2 39.015,4.4 40,4.4 40.615,5.015 J13.3@40.615,5.775
  L8 w0.12: v1(18.7,53.9) 18.7,53.5 18.4,53.2 18.4,51.8 17.5,50.9 17.5,49.9 16.8,49.2 16.8,48.1 15.9,47.2 15.9,44 15.7,43.8 15.7,42.7 15.2,42.2 15.2,40 15,39.8 15,34.956 17.066,32.89 17.3,32.89 18.515,31.675 18.515,31.441 19.8,30.156 19.8,29.8 24.1,25.5 24.1,23.4 24.4,23.1 24.4,17.456 25,16.856 25,15.1 25.815,14.285 25.815,11.641 26.1,11.356 26.1,10.7 27.4,9.4 27.7,9.4 28.6,8.5 28.856,8.5 32.656,4.7 33.396,4.7 34.086,4.01 37.61,4.01 v1(37.8,4.2)
  L10 w0.114: v1(18.7,53.9) R143.1@18.7,54.6 19.1,54.6 19.2,54.5 19.2,54.2 19.7,53.7 R152.2@19.7,53.4
SD2_CMD_R: R152.1 U1.F19 | length 4.3
  L1 w0.114: v1(24,53.7) U1.F19@24.4,53.3
  L10 w0.114: R152.1@20.7,53.4 21.4,54.1 23.6,54.1 v1(24,53.7)
SD2_DATA0: J13.7 U1.A22 | length 75.2
  L1 w0.114: v1(19.4,55.8) 19.5,55.7 U1.A22@20.4,55.7 ; v1(36.2,4.7) 36.215,4.715 J13.7@36.215,5.775
  L8 w0.12: v1(19.4,55.8) 19,55.4 19,54.8 19.4,54.4 19.4,54 19,53.6 19,51.944 17.915,50.859 17.915,49.7 17.585,49.37 17.585,48.285 16.7,47.4 16.7,46 16.5,45.8 16.5,43.9 16.2,43.6 16.2,42.6 15.705,42.105 15.705,40.805 15.515,40.615 15.515,39.985 15.8,39.7 15.8,39.4 15.41,39.01 15.41,37.58 15.8,37.19 15.8,35.4 16,35.2 16,34.8 18.1,32.7 18.6,32.7 19.3,32 19.3,31.456 20.255,30.501 20.255,30.045 22.565,27.735 23.565,27.735 24.1,27.2 24.1,26.5 25.7,24.9 25.7,24.4 25.5,24.2 25.1,24.2 24.9,24 24.9,22.9 25.15,22.65 25.45,22.65 25.7,22.4 25.7,22 25.2,21.5 25.2,21.1 25.4,20.9 25.8,20.9 26,20.7 26,20.3 25.8,20.1 24.9,20.1 24.7,19.9 24.7,19.5 24.9,19.3 25.9,19.3 26.1,19.1 26.1,18.7 25.9,18.5 24.9,18.5 24.7,18.3 24.7,17.9 24.9,17.7 25.7,17.7 26,17.4 26,15.1 26.3,14.8 26.3,12.244 26.585,11.959 26.585,10.771 27.441,9.915 27.985,9.915 28.9,9 29.444,9 31.585,6.859 31.585,6.415 32.6,5.4 34.4,5.4 34.6,5.2 34.6,4.6 34.8,4.4 35.2,4.4 35.4,4.6 35.4,5.2 35.6,5.4 36,5.4 36.2,5.2 v1(36.2,4.7)
SD2_DATA1: J13.8 U1.E20 | length 75.2
  L1 w0.114: v1(23.2,54.5) U1.E20@23.6,54.1 ; v1(33.8,6.6) 34.6,6.6 35.115,6.085 J13.8@35.115,5.775
  L8 w0.12: v1(23.2,54.5) 23.045,54.5 22.66,54.885 21.66,54.885 20.385,53.61 20.385,50.185 20.1,49.9 19.9,49.9 18.7,48.7 18.7,45.4 17.785,44.485 17.785,41.485 17.2,40.9 17.2,40.3 17.515,39.985 17.515,36.629 18.9,35.244 18.9,34.5 22,31.4 22,30.4 22.4,30 22.4,29.556 22.841,29.115 24.685,29.115 26.2,27.6 26.2,26.844 27.3,25.744 27.3,25.3 26.9,24.9 26.9,24.5 27.2,24.2 28.1,24.2 28.3,24 28.3,23.6 28.1,23.4 27.6,23.4 27.4,23.2 27.4,22.8 27.6,22.6 28.3,22.6 28.5,22.4 28.5,22 28.3,21.8 27.2,21.8 27,21.6 27,21.2 27.2,21 28.3,21 28.5,20.8 28.5,20.4 28.3,20.2 27.6,20.2 27.4,20 27.4,19.6 27.6,19.4 28.3,19.4 28.5,19.2 28.5,18.7 27.425,17.625 27.425,12.183 28.367,11.242 28.858,11.242 29.108,10.992 29.108,10.5 29.308,10.3 29.6,10.3 30.4,11.1 30.7,11.1 31,10.8 31,10.6 30.4,10 30.4,9.7 30.7,9.4 31,9.4 31.8,10.2 32.2,10.2 32.5,9.9 32.5,9.5 32,9 32,8.7 32.3,8.4 32.8,8.4 33.1,8.1 33.1,7.6 33.8,6.9 v1(33.8,6.6)
SD2_DATA2: J13.1 U1.A23 | length 75.2
  L1 w0.114: v1(19.8,56.5) U1.A23@20.4,56.5 ; v1(39.2,3.9) 39.9,3.2 41.6,3.2 42.815,4.415 J13.1@42.815,5.775
  L8 w0.12: v1(19.8,56.5) 19.785,56.485 19.785,55.641 19.615,55.471 19.615,55.141 19.8,54.956 19.8,53.9 19.4,53.5 19.4,51.7 18.744,51.044 18.744,49.944 17.9,49.1 17.9,48.1 17.485,47.685 17.485,46.085 17,45.6 17,43.9 16.7,43.6 16.7,42.544 16.1,41.944 16.1,40.629 16.285,40.444 16.285,39.285 15.7,38.7 15.7,38.3 16.3,37.7 16.3,35.7 16.5,35.5 16.5,34.9 18.2,33.2 18.6,33.2 19.815,31.985 19.959,31.985 20.685,31.259 20.685,30.471 21.4,29.756 21.4,29.4 22.62,28.18 22.626,28.18 22.741,28.065 23.891,28.065 25.1,26.856 25.1,26 26.035,25.065 26.035,21.165 26.5,20.7 26.5,15.7 26.673,15.527 ; 26.673,12.267 26.865,12.075 26.865,11.579 29.044,9.4 29.6,9.4 31.4,7.6 31.9,7.6 32.385,7.115 32.385,6.471 33.056,5.8 37.9,5.8 39.2,4.5 v1(39.2,3.9) ; 26.675,12.267 26.675,15.527
SD2_DATA3: J13.2 U1.B22 | length 75.2
  L1 w0.114: v1(20.8,55.3) U1.B22@21.2,55.7 ; v1(40,3.9) 40.2,3.7 41.4,3.7 41.8,4.1 41.8,4.644 41.615,4.829 41.615,6.075 J13.2@41.715,6.175
  L8 w0.12: v1(20.8,55.3) 20.8,54.9 20.2,54.3 20.2,53.821 19.8,53.421 19.8,50.9 19.615,50.715 19.615,50.2 18.3,48.885 18.3,47.9 17.8,47.4 17.8,46.7 18.3,46.2 18.3,45.8 17.4,44.9 17.4,42.9 17,42.5 17,41.5 16.8,41.3 16.8,39.1 17.1,38.8 17.1,37.9 16.7,37.5 16.7,36.1 17.3,35.5 17.3,34.7 17.6,34.4 18.4,34.4 18.7,34.1 18.7,33.6 19.4,32.9 20.044,32.9 20.5,32.444 20.5,32.1 21,31.6 21,30.8 21.9,29.9 21.9,29.4 22.465,28.835 23.121,28.835 23.4,28.556 23.9,28.556 24.556,27.9 25.3,27.9 25.7,27.5 25.7,26.056 26,25.756 26.444,25.756 26.659,25.541 26.659,25.159 26.5,25 26.5,24.4 26.8,24.1 26.8,23.6 26.5,23.3 26.5,22.9 26.9,22.5 26.9,22.2 26.45,21.75 26.45,21.35 27.05,20.75 27.05,12.286 ; v1(40,3.9) 40,4.4 38.185,6.215 33.441,6.215 33.185,6.471 33.185,7.015 32.2,8 31.6,8 31.4,8.2 31.4,8.8 31.172,9.028 30.628,9.028 29.726,9.93 29.07,9.93 27.145,11.855 27.145,12.191 ; 27.05,12.286 27.145,12.191 ; 27.05,12.286 27.145,12.191
SD2_WP: R139.2 R151.1 U1.T1 | length 4.2
  L1 w0.114: U1.T1@32.4,38.9 32.5,38.9 34.3,37.1 R151.1@34.3,37 34.3,36.5 34,36.2 R139.2@34,35.7
SENSE_1V5: R302.1 R303.2 U31.5 | length 3.5
  L10 w0.3: R302.1@1.4,43.5 2.3,44.4 R303.2@2.3,44.6 2.6,44.6 3.6,43.6 U31.5@3.6,43.25
SPLIT: C313.1 R246.1 R248.2 R249.2 | length 3.1
  L10 w0.4: v1(2.9,47.3) 3.3,46.9 R246.1@3.3,46.7 ; v1(5.75,46.1) 6.3,46.65 R249.2@6.3,46.7 ; C313.1@7.4,46.8 7.4,47 v1(7.1,47.3) 7.4,47.6 R248.2@7.4,48.1
SPLIT_R: R248.1 U19.5
SS_1V375: R342.2 U30.7 | length 1.6
  L1 w0.4: v1(12,33.05) 12.05,33 R342.2@12.7,33
  L10 w0.23: v1(12,33.05) 12.2,33.25 U30.7@12.79,33.25
SS_3V3_HDR: R406.2 U36.7 | length 1.1
  L10 w0.23: R406.2@11.4,90.5 11.45,90.45 U36.7@12.49,90.45
STBY_OR_USER_LED_3: D36.1 R391.1 U6.7 | length 6.4
  L10 w0.114: U6.7@21.95,18.875 22.525,18.875 22.8,18.6 22.8,17.66 21.915,16.775 21.915,16.044 22.67,15.289 22.67,14.37 R391.1@22.3,14
SW1CFB: R384.2 U9.13 | length 1.6
  L1 w0.3: v1(24.7,30.9) 24.85,30.75 U9.13@24.85,30.15
  L10 w0.4: R384.2@24.6,31.6 24.6,31 v1(24.7,30.9)
SW1CLX: L8.2 U9.11
SW1LX: L1.1 U9.8 U9.9
SW2LX: L10.1 U9.22
SW3LX: L2.1 U9.35 U9.36
SW4LX: L9.1 U9.21
SW_EP: U32.3 U32.4 U32.5 U32.6 U32.14
SWBSTLX: D18.2 L11.2 U9.46
SYNC_1V375: R335.1 R338.2 U30.4 | length 11.4
  L10 w0.114: R335.1@5.7,27.5 5.8,27.6 R338.2@6.8,27.6 6.8,27.4 7.62,26.58 7.98,26.58 8.9,27.5 10.36,27.5 11.16,28.3 11.16,29.96 11.915,30.715 12.515,30.715 13.4,31.6 U30.4@13.45,31.6
SYNC_3V3_HDR: R398.1 R401.2 U36.4 | length 2.7
  L10 w0.114: U36.4@13.15,88.8 13.15,88.35 13.7,87.8 R398.1@13.7,87.5 R401.2@13.7,86.3
TAMPER: R55.1 U1.E11 | length 1.2
  L1 w0.114: v1(23.2,47.3) U1.E11@23.6,46.9
  L10 w0.114: v1(23.2,47.3) 23.4,47.1 R55.1@23.735,47.1
TCT0: C272.2 J6.12 | length 1.7
  L10 w0.4: J6.12@22.296,74.213 22.7,73.809 C272.2@22.7,72.7
TCT1: C274.2 J6.6 | length 1.6
  L10 w0.4: J6.6@21.28,76.753 J6.6@21.327,76.8 ; J6.6@21.28,77.053 22.753,77.053 C274.2@22.8,77.1
TCT2: C275.2 J6.1 | length 2.6
  L10 w0.4: C275.2@9.2,78.5 9.242,78.5 9.625,78.117 J6.1@10.689,77.053 ; J6.1@10.647,77.053 J6.1@10.689,77.053 ; J6.1@11.12,77.053 J6.1@10.689,77.053
TCT3: C276.2 J6.7 | length 1.8
  L10 w0.4: C276.2@10.104,72.7 J6.7@10.104,74.513
TEMP_ADD0: R258.2 R259.2 U24.5 | length 7.3
  L1 w0.114: v1(26.7,92.5) 26.4,92.2 R259.2@25.9,92.2 25.285,91.585 25.285,89.571 26.8,88.056 U24.5@26.8,87.75
  L10 w0.114: v1(26.7,92.5) 27.4,91.8 R258.2@27.5,91.8
TEMP_ALERT: R257.1 U1.E24 U24.3 | length 44.6
  L1 w0.114: v1(22.8,59.5) 22.8,59.244 23.185,58.859 23.185,58.855 23.21,58.83 23.21,57.69 U1.E24@23.6,57.3 ; v1(26.7,88.7) 26.656,88.7 25.85,89.506 25.85,91.008 26.622,91.78 26.98,91.78 R257.1@27.4,92.2
  L3 w0.12: v1(22.8,59.5) 23.185,59.885 23.729,59.885 24,60.156 24,65.056 28.02,69.076 28.02,69.864 28.641,70.485 29.185,70.485 31,72.3 32.5,72.3 32.8,72.6 32.8,73.8 32.285,74.315 32.285,76.215 31,77.5 31,78.8 29.9,79.9 v1(29.9,82.3)
  L10 w0.114: v1(26.7,88.7) 26.7,86.3 28.1,84.9 28.1,84.1 v1(29.9,82.3)
TEST_MODE: R56.2 U1.E12 | length 3.7
  L1 w0.114: v1(22.4,48.1) 23,48.1 23.4,47.7 U1.E12@23.6,47.7
  L10 w0.114: v1(22.4,48.1) 22.8,47.7 22.8,46.135 R56.2@22.665,46
TRD0_N: J6.10 U7.3 | length 9.3
  L1 w0.1: U7.3@17.35,70.54 17.35,70.94 17.44,71.03 17.44,71.26 17.2,71.5 17.2,72.544 17.617,72.961 18.383,72.961 18.8,72.544 18.8,72.009 19.159,71.65 19.5,71.65 19.74,71.89 19.74,72.26 v1(19.6,72.4)
  L10 w0.1: J6.10@18.232,74.513 18.475,74.513 19.088,73.9 19.088,73.559 19.74,72.907 19.74,72.54 v1(19.6,72.4)
TRD0_P: J6.11 U7.2 | length 9.3
  L1 w0.1: U7.2@17.85,70.54 17.85,70.94 17.76,71.03 17.76,71.393 17.52,71.633 17.52,72.412 17.75,72.641 18.25,72.641 18.48,72.412 18.48,71.877 19.027,71.33 19.633,71.33 20.06,71.757 20.06,72.26 v1(20.2,72.4)
  L10 w0.1: v1(20.2,72.4) 20.06,72.54 20.06,73.04 19.408,73.692 19.408,73.9 20.021,74.513 J6.11@20.264,74.513
TRD1_N: J6.5 U7.6 | length 9.3
  L1 w0.1: U7.6@15.85,70.54 15.85,70.95 16.03,71.13 16.03,73.483 16.48,73.933 16.48,75.1 16.18,75.4 v1(16.1,75.4)
  L10 w0.1: v1(16.1,75.4) 16.172,75.4 16.372,75.2 17.409,75.2 19.248,77.039 J6.5@19.248,77.053
TRD1_P: J6.4 U7.5 | length 9.3
  L1 w0.1: U7.5@16.35,70.54 16.35,73.35 16.8,73.8 16.8,75.5 v1(16.5,75.8)
  L10 w0.1: v1(16.5,75.8) 16.5,75.72 16.7,75.52 17.277,75.52 18.22,76.463 18.22,76.88 18.047,77.053 J6.4@17.216,77.053
TRD2_N: J6.2 U7.8 | length 9.3
  L1 w0.1: v1(14.8,72.88) 14.94,72.74 14.94,72.54 14.48,72.08 14.48,71.6 14.94,71.14 14.94,71.03 14.85,70.94 U7.8@14.85,70.54
  L10 w0.1: J6.2@13.152,77.053 13.655,77.053 14.008,76.7 14.008,75.858 14.421,75.445 14.987,75.445 15.84,74.592 15.84,74.249 15.642,74.051 15.351,74.051 14.94,73.64 14.94,73.02 v1(14.8,72.88)
TRD2_P: J6.3 U7.7 | length 9.3
  L1 w0.1: U7.7@15.35,70.54 15.35,70.94 15.26,71.03 15.26,71.273 14.8,71.733 14.8,71.947 15.26,72.407 15.26,72.74 v1(15.4,72.88)
  L10 w0.1: J6.3@15.184,77.053 14.681,77.053 14.328,76.7 14.328,75.99 14.553,75.765 15.12,75.765 16.16,74.725 16.16,74.117 15.774,73.731 15.483,73.731 15.26,73.507 15.26,73.02 v1(15.4,72.88)
TRD3_N: J6.9 U7.11 | length 9.3
  L1 w0.1: v1(11.1,72.5) 11.2,72.5 11.48,72.78 11.72,72.78 12.12,72.38 12.38,72.38 12.78,72.78 12.977,72.78 13.53,72.227 13.53,71.1 13.35,70.92 U7.11@13.35,70.54
  L10 w0.1: v1(11.1,72.5) 13.1,72.5 13.5,72.9 13.5,73.845 J6.9@14.168,74.513
TRD3_P: J6.8 U7.10 | length 9.3
  L1 w0.1: v1(11.1,73.1) 13.109,73.1 13.85,72.359 U7.10@13.85,70.54
  L10 w0.1: v1(11.1,73.1) 11.2,73.1 11.48,72.82 12.967,72.82 13.18,73.033 13.18,73.9 12.567,74.513 J6.8@12.136,74.513
TS_X+: C177.1 D37.5 FB15.2 J10.1 | length 11.7
  L10 w0.3: J10.1@5.15,11.125 5.7,10.575 5.7,9.3 6.2,8.8 8.1,8.8 8.36,9.06 8.36,10.94 8.15,11.15 D37.5@8.15,11.7 8.16,11.69 8.71,11.69 C177.1@9.2,11.2 9.5,11.2 10.31,10.39 10.31,9.31 FB15.2@10.2,9.2
TS_X+_B: FB15.1 R393.2 U6.21 | length 19.2
  L8 w0.3: v1(9.9,8.2) 9.2,8.9 9.2,13.2 11.7,15.7 12.9,15.7 13.8,16.6 13.8,20.45 v1(13.5,20.75)
  L10 w0.3: FB15.1@9.2,9.2 9.1,9.1 R393.2@9.1,8.2 v1(9.9,8.2) ; v1(13.5,20.75) 14.6,20.75 14.675,20.825 U6.21@15.25,20.825
TS_X-: C178.1 D37.1 FB25.2 J10.2 | length 3.9
  L10 w0.3: J10.2@5.15,12.375 5.521,12.375 6.234,11.662 D37.1@6.65,11.662 6.7,11.612 C178.1@6.7,10.6 FB25.2@7.7,10.6
TS_X-_B: FB25.1 R394.2 U6.22 | length 18.7
  L8 w0.3: v1(7.2,10.1) 7.2,10.9 6.5,11.6 6.5,14.428 7.3,15.228 7.3,17.8 9.1,19.6 v1(10.9,19.6)
  L10 w0.3: v1(7.2,10.1) FB25.1@7.7,9.6 ; v1(10.9,19.6) 10.9,19.728 11.6,20.428 R394.2@11.6,20.6 12.265,21.265 14.464,21.265 14.484,21.285 14.509,21.285 14.699,21.475 U6.22@15.25,21.475
TS_Y+: C210.1 D37.4 FB28.2 J10.4 | length 11.1
  L10 w0.3: J10.4@5.15,14.875 6.15,15.875 7.725,15.875 8.6,15 8.6,14 8.2,13.6 D37.4@8.2,12.71 ; D37.4@8.2,12.7 D37.4@8.15,12.7 8.15,12.71 D37.4@8.2,12.71 ; FB28.2@11.6,14.8 10.728,14.8 9.2,13.272 C210.1@9.2,13.2 8.71,12.71 D37.4@8.2,12.71
TS_Y+_B: FB28.1 R396.2 U6.24 | length 11.9
  L8 w0.3: v1(10.8,16.6) 11.6,16.6 12.3,17.3 12.3,18.072 12.603,18.375 12.947,18.375 13.275,18.703 13.275,20.097 12.8,20.572 12.8,21.9 v1(13.1,22.2)
  L10 w0.3: v1(10.8,16.6) 11,16.8 R396.2@11.6,16.8 FB28.1@11.6,15.8 ; v1@13.1,22.205 14.128,22.205 14.128,22.207 14.697,22.775 U6.24@15.25,22.775
TS_Y-: C179.1 D37.3 FB27.2 J10.3 | length 4
  L10 w0.3: J10.3@5.15,13.625 5.575,13.625 6.462,12.738 D37.3@6.65,12.738 6.65,13.75 C179.1@6.7,13.8 7.6,13.8 FB27.2@7.7,13.7
TS_Y-_B: FB27.1 R395.2 U6.23 | length 15.9
  L8 w0.3: v1(7.2,14.3) 8.2,15.3 8.2,16.3 9.1,17.2 11,17.2 11.5,17.7 11.5,18.8 12.2,19.5 12.2,20 v1(11,21.2)
  L10 w0.3: v1(7.2,14.3) FB27.1@7.7,14.8 ; v1(11,21.2) 11.5,21.7 R395.2@11.6,21.7 11.625,21.725 14.274,21.725 14.294,21.745 14.319,21.745 14.699,22.125 U6.23@15.25,22.125
UART1_CTS: Q8.4 R60.1 R375.1 U1.G21 | length 66.5
  L1 w0.114: U1.G21@25.2,54.9 25.6,55.3 v1(26.4,55.3)
  L3 w0.12: v1(26.4,55.3) 26,55.7 26,57.1 25.4,57.7 25.4,65.2 29.2,69 29.2,69.444 31.456,71.7 33,71.7 33.615,72.315 33.615,78.285 v1(33.4,78.5) ; v1(33.956,88.8) 35.156,90 39.5,90 39.9,90.4 46.8,90.4 48.3,91.9 49.6,91.9 50.2,92.5 v1(54.4,92.5)
  L10 w0.114: v1(33.4,78.5) 33.8,78.9 33.8,81.9 32.9,82.8 32.9,86.8 33.956,87.856 v1(33.956,88.8) ; R60.1@51.7,93.7 R375.1@52.7,93.7 52.7,92.8 53.15,92.35 Q8.4@53.65,92.35 54.25,92.35 v1(54.4,92.5)
UART1_CTS_FTDI: D31.1 J3.6 Q8.3 R60.2 | length 39.3
  L8 w0.12: v1(49.95,93.7) 51.4,93.7 54.1,91 55.4,91 55.8,90.6 57.5,90.6 59.5,88.6 62.1,88.6 63.5,87.2 64.06,87.2 65,86.26 65,85.8 65.5,85.3 65.5,83.7 66.2,83 66.2,75.5 66.4,75.3 66.4,72.7 v1(66.9,72.2)
  L10 w0.114: v1(49.95,93.7) R60.2@50.7,93.7 50.7,93.2 51.55,92.35 Q8.3@51.75,92.35 ; v1(66.9,72.2) 66,73.1 D31.1@66,73.15 66.05,73.15 66.7,73.8 67.84,73.8 J3.6@68.04,73.6
UART1_RTS: Q11.1 R376.1 R378.1 U1.G20 | length 69.1
  L1 w0.114: U1.G20@25.2,54.1 v1(25.6,53.7)
  L3 w0.12: 25.6,54.64 v1(25.6,53.7) 25.6,56.7 24.8,57.5 24.8,65.2 28.4,68.8 28.4,69.444 28.656,69.7 28.944,69.7 31.264,72.02 32.82,72.02 33.2,72.4 33.2,78 33,78.2 33,78.9 v1(33.4,79.3) ; v1(33.1,87.9) 35.4,87.9 36.6,89.1 50.8,89.1 52.75,91.05 v1(55.9,91.05)
  L10 w0.114: v1(33.1,87.9) 32,86.8 32,83 33.4,81.6 v1(33.4,79.3) ; R376.1@55.9,89.8 R378.1@56.9,89.8 56.9,90.9 56.75,91.05 Q11.1@56.65,91.05 v1(55.9,91.05)
UART1_RTS_FTDI: D32.1 J3.2 Q11.6 R377.1 R378.2 | length 16.1
  L8 w0.12: v1(59.3,90.9) 60.4,90.9 61.2,90.1 62.1,90.1 v1(64.6,87.6)
  L10 w0.114: R377.1@59.2,89.8 R378.2@57.9,89.8 57.9,90.6 58.35,91.05 Q11.6@58.55,91.05 59.15,91.05 v1(59.3,90.9) ; v1(64.6,87.6) 65.25,87.6 D32.1@66.15,86.7 66.77,86.08 66.77,85.474 68.04,84.204 J3.2@68.04,83.76
UART1_RXD: Q8.1 R370.1 R373.1 U1.M3 | length 85.2
  L1 w0.114: v1(26.9,37.4) 27.356,37.4 27.856,37.9 28.2,37.9 28.8,38.5 28.8,40.1 U1.M3@29.2,40.5
  L3 w0.12: v1(26.9,37.4) 27.3,37.8 27.3,38.7 26.795,39.205 26.795,40.249 26.544,40.5 26.215,40.5 26.015,40.7 26.015,43.459 26.241,43.685 26.529,43.685 27.359,44.515 28.159,44.515 28.41,44.766 28.41,53.834 28.159,54.085 27.871,54.085 27.585,54.371 27.585,56.315 27.4,56.5 27.056,56.5 26.8,56.756 26.8,58 27.2,58.4 27.2,59.61 27.8,60.21 27.8,66.2 28.9,67.3 29.2,67.3 29.5,67.6 29.5,68.8 29.7,69 29.7,69.4 30.8,70.5 31.356,70.5 32.216,71.36 33.56,71.36 34.1,71.9 34.1,74.5 34.5,74.9 34.5,76.5 34.2,76.8 34.2,78.1 v1(34.7,78.6) ; v1(36.5,88.3) 36.7,88.5 46.7,88.5 46.915,88.285 51.385,88.285 v1(52.2,89.1)
  L10 w0.114: v1(34.7,78.6) 34.7,83.1 33.9,83.9 33.9,85.7 35.3,87.1 v1(36.5,88.3) ; R370.1@50.3,91.6 51,91.6 51.55,91.05 Q8.1@51.75,91.05 51.75,90.25 R373.1@52.2,89.8 v1(52.2,89.1)
UART1_RXD_FTDI: D4.1 J3.4 Q8.6 R373.2 | length 27.6
  L8 w0.12: v1(54.3,89.7) 54.7,90.1 57.3,90.1 59.4,88 62.144,88 64.82,85.324 64.82,83.92 64.385,83.485 63.485,83.485 v1(62.2,82.2)
  L10 w0.114: Q8.6@53.65,91.05 53.65,90.65 53.2,90.2 R373.2@53.2,89.8 53.3,89.7 v1(54.3,89.7) ; v1(62.2,82.2) 63.75,80.65 D4.1@66,80.65 66.65,80.65 68.04,79.26 J3.4@68.04,78.7
UART1_TXD: Q11.4 R371.1 R374.1 U1.M1 | length 91.5
  L1 w0.114: v1(28.1,37.4) 28.2,37.4 29.135,38.335 29.135,38.835 U1.M1@29.2,38.9
  L3 w0.12: v1(28.1,37.4) 27.6,37.9 27.6,38.82 27.085,39.335 27.085,40.37 26.8,40.655 26.8,43.444 27.071,43.715 28.315,43.715 29.215,44.615 29.215,53.425 28.4,54.24 28.4,56.3 28.185,56.515 27.841,56.515 27.615,56.741 27.615,56.785 27.6,56.8 27.6,58.9 28.2,59.5 28.2,65.7 28.9,66.4 29.244,66.4 29.9,67.056 29.9,68.656 30.144,68.9 30.144,69.289 31.056,70.2 31.6,70.2 32.4,71 33.8,71 34.5,71.7 34.5,74.1 35,74.6 35,77.5 v1(34.7,77.8) ; v1(35,88.3) 36.3,89.6 39.8,89.6 40.1,89.9 47.4,89.9 48.9,91.4 50.3,91.4 51,92.1 58.9,92.1 v1(59.3,92.5)
  L10 w0.114: v1(34.7,77.8) 34.2,78.3 34.2,82.2 33.335,83.065 33.335,85.835 35,87.5 v1(35,88.3) ; R374.1@56.8,93.7 R371.1@57.8,93.7 57.8,92.9 58.35,92.35 Q11.4@58.55,92.35 59.15,92.35 v1(59.3,92.5)
UART1_TXD_FTDI: D8.1 J3.5 Q11.3 R372.1 R374.2 | length 29.2
  L8 w0.12: v1(57.4,92.5) 58.4,91.5 58.4,91 59.9,89.5 61.9,89.5 63.7,87.7 63.956,87.7 64.556,87.1 65.2,87.1 66.2,86.1 66.2,84 66.8,83.4 66.8,80.5 67.1,80.2 67.1,79.318 66.6,78.818 v1(66.6,77.1)
  L10 w0.114: R372.1@55.1,92.1 55.1,93.5 55.3,93.7 R374.2@55.8,93.7 55.8,93.3 56.65,92.45 Q11.3@56.65,92.35 57.25,92.35 v1(57.4,92.5) ; v1(66.6,77.1) 66,76.5 D8.1@66,76.25 66.11,76.14 J3.5@68.04,76.14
